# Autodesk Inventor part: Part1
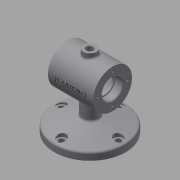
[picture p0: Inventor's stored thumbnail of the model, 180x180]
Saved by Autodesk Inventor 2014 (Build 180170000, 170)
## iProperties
Created: 2018-12
Part Number: Part1
Material: Generic
Document SubType Name: Modeling
Designer: kh
Density: 1 g/cm^3
Appearance: Default
Author: kh
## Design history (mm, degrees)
sketch "Sketch1"
  geometry: C1 r 55 at (0, 0); 1 further point
  constraints: 1 centre point, 1 coincident
  dimensions: "d0" = 110 diameter of C1
extrude "Extrusion1" new body sketch "Sketch1" distance "d1" = 11; taper "d2" = 0 deg
sketch "Sketch2"
  geometry: L1 (-59.309, 75)-(74.881, 75); L2 (-55, 0)-(55, 0) reference; L3 (-35, 75)-(35, 75); L4 (35, 75)-(35, 105); L5 (35, 105)-(-35, 105); L6 (-35, 105)-(-35, 75); L7 (0, 0)-(0, 105)
  constraints: 12 end point, 2 horizontal, 2 parallel, 2 perpendicular, 1 midpoint, 1 point on line, 1 other
  dimensions: "d4" = 75 distance between parallel lines of L2 L1; "d5" = 60 diameter of L5 L1; "d6" = 70 distance between parallel lines of L4 L6
revolve "Revolution1" sketch "Sketch2" stored, may be unused: angle "d7" = 90 deg
sketch "Sketch3"
  geometry: C1 r 12 at (0, 0); 1 further point
  constraints: 1 centre point, 1 coincident
  dimensions: "d8" = 24 diameter of C1
extrude "Extrusion2" join sketch "Sketch3" stored distance "d9" = 10; taper "d10" = 0 deg
sketch "Sketch4"
  geometry: L1 (12, 11)-(12, 45) reference; L2 (55, 11)-(-55, 11) reference; L3 (-12, 11)-(-12, 45) reference; L4 (0, 25.737)-(55, 11); L5 (-35, 105)-(35, 105) reference; L6 (0, 0)-(0, 105); L7 (0, 11)-(55, 11); L8 (0, 25.737)-(0, 11)
  constraints: 8 end point, 2 collinear, 2 midpoint, 2 point on line
  dimensions: "d11" = 165 deg angle of L2 L4
revolve "Revolution2" sketch "Sketch4" stored, may be unused: angle "d12" = 90 deg
sketch "Sketch6"
  geometry: L1 (-63.947, 75)-(66.267, 75); L2 (-35, 105)-(35, 105) reference; L3 (-35, 45)-(35, 45) reference; L4 (-55, 0)-(55, 0) reference; L5 (-35, 45)-(-35, 105) reference; L6 (35, 45)-(35, 105) reference; L7 (-35, 75)-(-23, 75); L8 (-23, 75)-(-23, 90.7); L9 (-23.3, 91)-(-35, 91); L10 (-35, 91)-(-35, 75); L11 (-23, 75)-(-20, 75); L12 (-20, 75)-(-20, 89); L13 (-20, 89)-(-23, 89); L14 (-23, 89)-(-23, 75); L15 (-20, 75)-(20, 75); L16 (20, 75)-(20, 97); L17 (17, 100)-(-17, 100); L18 (-20, 97)-(-20, 75); L19 (20, 75)-(23, 75); L20 (23, 75)-(23, 90.7); L21 (23, 89)-(20, 89); L22 (20, 89)-(20, 75); L23 (23, 75)-(35, 75); L24 (35, 75)-(35, 91); L25 (35, 91)-(23.3, 91); L26 (23, 91)-(23, 75); A1 r 0.3 centre (-23.3, 90.7) between (-23, 90.7) and (-23.3, 91); A2 r 0.3 centre (23.3, 90.7) between (23.3, 91) and (23, 90.7); A3 r 3 centre (-17, 97) between (-17, 100) and (-20, 97); A4 r 3 centre (17, 97) between (20, 97) and (17, 100); 4 further points
  constraints: 42 end point, 10 parallel, 9 point on line, 8 point on circle, 8 tangent, 6 horizontal, 5 perpendicular, 4 centre point, 2 equal radius, 1 midpoint
  dimensions: "d13" = 150 diameter of L4 L1; "d14" = 32 diameter of L9 L1; "d15" = 28 diameter of L13 L1; "d16" = 50 diameter of L17 L1; "d17" = 32 diameter of L25 L1; "d18" = 28 diameter of L21 L1; "d19" = 40 distance of point (20, 100) point (-20, 100); "d20" = 12 distance of point (-23, 91) L9.end; "d21" = 3 distance of L12.end L13.end; "d22" = 3 distance of L21.start L21.end; "d23" = 0.3 radius of A1; "d24" = 3 radius of A3
revolve "Revolution3" sketch "Sketch6" stored, may be unused: angle "d25" = 90 deg
sketch "Sketch8" dims "d27" = 88
  geometry: L1 (0, 0)-(0, 44); C1 r 4.5 at (0, 44); 2 further points
  constraints: 3 coincident, 2 end point, 1 centre point, 1 vertical, 1 vertical alignment, 2 other
  dimensions: "d28" = 9 diameter of C1
extrude "Extrusion3" cut sketch "Sketch8" distance "d29" = 16; taper "d30" = 0 deg
workplane "Work Plane3"
sketch "Sketch11"
  geometry: C1 r 4.5 at (0, 44) reference; C2 r 7 at (0, 44); 1 further point
  constraints: 1 centre point, 1 coincident
  dimensions: "d35" = 14 diameter of C2
extrude "Extrusion4" cut sketch "Sketch11" distance "d36" = 6; taper "d37" = 0 deg
pattern_circular "Circular Pattern1" dims angle "d39" = 360 deg
sketch "Sketch12" dims "d41" = 46
  geometry: L1 (0, 0)-(23, 0); C1 r 16 at (0, 0) reference; C2 r 30 at (0, 0) reference; 2 further points
  constraints: 2 coincident, 2 end point, 1 horizontal, 1 horizontal alignment, 2 other
hole "Hole1" sketch "Sketch12" at (23, 0) diameter "d42" = 3.242; stored, may be unused: countersink angle "d46" = 90 deg, drill point angle "d48" = 118 deg; dims "d43" = 8, "d44" = 4, "d45" = 2, "d47" = 10
pattern_circular "Circular Pattern2" dims angle "d50" = 360 deg
mirror "Mirror1"
workplane "Work Plane4"
sketch "Sketch13"
  geometry: L1 (0, 0)-(0, 55); C1 r 10 at (0, 0); C2 r 5 at (0, 0); 1 further point
  constraints: 2 centre point, 2 coincident, 2 end point, 1 vertical, 1 vertical alignment, 1 other
  dimensions: "d53" = 20 diameter of C1; "d54" = 10 diameter of C2
extrude "Extrusion5" join sketch "Sketch13" stored distance "d55" = 6; taper "d56" = 0 deg
sketch "Sketch14"
  geometry: C1 r 5 at (0, 0); 1 further point
  constraints: 1 centre point, 1 coincident
  dimensions: "d57" = 10 diameter of C1
extrude "Extrusion6" cut sketch "Sketch14" stored distance "d58" = 6; taper "d59" = 0 deg
chamfer "Chamfer1" distance "d60" = 1; stored, may be unused: second distance "d61" = 2, angle "d62" = 45 deg
workplane "Work Plane5"
sketch "Sketch15"
  geometry: L1 (-24.887, 3.602)-(24.887, 3.602); L2 (24.887, 3.602)-(24.887, -3.602); L3 (24.887, -3.602)-(-24.887, -3.602); L4 (-24.887, -3.602)-(-24.887, 3.602); L5 (-24.887, 3.602)-(24.887, -3.602); L6 (-35, 30)-(-35, -30) reference; L7 (35, 30)-(-35, 30) reference; 2 further points
  constraints: 2 end point, 1 midpoint, 2 other
  dimensions: "d63" = 35 distance from line of point (0, 0) L6; "d64" = 30 distance from line of point (0, 0) L7
emboss "Emboss1" sketch "Sketch15" dims "d65" = 0.5, "d66" = 0
fillet "Fillet1" dims "d67" = 3
fillet "Fillet2" dims "d68" = 3
fillet "Fillet3" dims "d69" = 3
body "Solid1"
node "Projected Loop2"
other parameters: "d52" = 112
